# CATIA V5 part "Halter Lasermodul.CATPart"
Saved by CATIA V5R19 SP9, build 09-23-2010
Part number: Halter Lasermodul
Bounding box of the stored display mesh (mm): x -17 to 10, y -10 to 17, z -5 to 0
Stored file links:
  D:\Temporäre Sachen\Lasermodul KY-008 with mounting for adjustment\Halter Lasermodul.CATPart
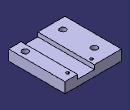
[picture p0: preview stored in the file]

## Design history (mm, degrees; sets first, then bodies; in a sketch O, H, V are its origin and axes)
Parameters
  inch2mm = 2.54 mm
Body1 (main body)
  Sketch1 on xy-plane, origin (0, 0, 0), H (1, 0, 0), V (0, 1, 0)
    line L1 (-17, -10) -> (10, -10)
    line L2 (10, -10) -> (10, 17)
    line L3 (10, 17) -> (-17, 17)
    line L4 (-17, 17) -> (-17, -10)
    distance L1 L3 = 27 (reference)
    distance H L3 = 17
    distance V L2 = 10
    distance V L4 = 17
    distance H L1 = 10
    horizontal: L1 H, L3 H
    vertical: L2 V, L4 V
  Pad1: profile Sketch1, direction (0, 0, -1), length 5
  Sketch2 on xy-plane, origin (0, 0, 0), H (1, 0, 0), V (0, 1, 0)
    point P1 (-11, 10)
    construction line L1 (-11, 10) -> (7, 10)
    construction line L2 (7, 10) -> (7, -5)
    construction line L3 (7, -5) -> (-11, -5)
    construction line L4 (-11, -5) -> (-11, 10)
    axis line L5 (-5.715, 14) -> (5.715, 14)
    point P5 (-5.715, 14)
    point P6 (5.715, 14)
    distance L2 L4 = 18 (reference)
    distance H L1 = 10
    distance H L3 = 5
    distance P5 P6 = 11.43 {= 4.5*inch2mm}
    distance H L5 = 14
    distance V L2 = 7
    distance V L4 = 11
    horizontal: L1 H, L3 H, L5 H
    vertical: L2 V, L4 V
    symmetry: P5 P6 V
  Sketch3 on start face of Pad1, origin (8.9043, 14.4878, 0), H (1, 0, 0), V (0, 1, 0)
    point P1 (-19.9043, -4.4878)
    projected point E1 (-19.9043, -4.4878) from Sketch2.P1
    coincidence: E1 P1
  Hole1: placed by Sketch3, at (-11, 10, 0) direction (0, 0, -1), diameter 3, depth 10
  UserPattern1: of Hole1, copies 5, at the points of Sketch2
  Sketch4 on zx-plane, origin (0, 0, 0), H (-1, 0, 0), V (0, 0, 1)
    line L1 (4, 2) -> (4, -2)
    line L2 (4, -2) -> (-4, -2)
    line L3 (-4, -2) -> (-4, 2)
    line L4 (-4, 2) -> (4, 2)
    distance L2 L4 = 4
    distance L1 L3 = 8
    vertical: L1 V, L3 V
    horizontal: L2 H, L4 H
    equidistance: L1 L3 O, L2 L4 O
  Pocket1: profile Sketch4, direction (0, -1, 0), length 18, mirrored extent
  Sketch5 on end face of Pad1, origin (-5.715, 14, -5), H (1, 0, 0), V (0, -1, 0)
    point P1 (0, 0)
    reference projected point E1 (0, 0) from Sketch2.P5
    coincidence: E1 P1
  Hole2: placed by Sketch5, at (-5.715, 14, -5) direction (0, 0, 1), diameter 1.5, depth 10
  UserPattern2: of Hole2, copies 5, at the points of Sketch2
